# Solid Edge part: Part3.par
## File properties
Author: Robert a Rhodes jr
Template: Normal.par
Last saved by: Cadcim
Revision: 4
Application: Solid Edge
Accuracy: 0.99
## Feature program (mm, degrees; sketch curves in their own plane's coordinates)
sketch for "unnamed Protrusion 1" #1 plane through (0, 0, 0) normal (0, 0, 1) x-axis (1, 0, 0)
  line (-42.48, -13.536) -> (53.136, -13.536)
  arc centre (53.136, -1.872) radius 11.664 from (53.136, 9.792) to (53.136, -13.536) cw
  line (53.136, 9.792) -> (-42.48, 9.792)
  arc centre (-42.48, -1.872) radius 11.664 from (-42.48, 9.792) to (-42.48, -13.536) ccw
sketch for "unnamed Protrusion 1" #2 plane through (0, 0, 0) normal (0, 0, 1) x-axis (1, 0, 0)
  circle centre (-42.48, -1.872) radius 7
sketch for "unnamed Protrusion 1" #3 plane through (0, 0, 0) normal (0, 0, 1) x-axis (1, 0, 0)
  circle centre (53.136, -1.872) radius 7
extrude "unnamed Protrusion 1" add finite 13 along -normal
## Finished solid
Body 1: solid body, 8 faces, 16 edges, 8 vertices.
  Faces by surface: cylinder 4, plane 4
  Edges by curve: circle 8, line 8
Bounding box of the edges (mm): 118.944 x 23.328 x 13.000, from (-54.144, -13.536, -13) to (64.8, 9.792, 0).
Cylindrical faces by radius (mm): R7 x2, R11.664 x2
Planar faces by outward normal: +y 1, +z 1, -y 1, -z 1
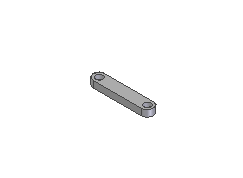
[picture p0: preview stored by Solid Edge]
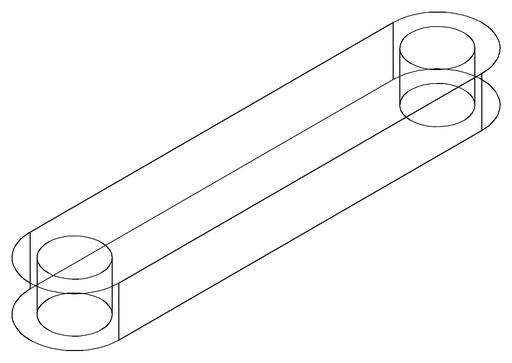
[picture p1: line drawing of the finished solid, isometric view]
